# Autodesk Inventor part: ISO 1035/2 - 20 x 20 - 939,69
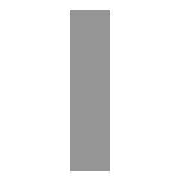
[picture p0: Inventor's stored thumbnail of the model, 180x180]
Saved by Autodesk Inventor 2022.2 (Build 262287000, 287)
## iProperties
IsCustomPart: 1
Created: 2025-02
Part Number: ISO 1035/2 - 20 x 20 - 939,69
Material: Acciaio, Dolce
Description: Barre in acciaio laminate a caldo - Parte 2: barre quadre
Document SubType Name: Modeling
Standard: ISO 1035/2
Designer: 18907419
Standard Revision: First edition 1980-10-15
Standards Organization: ISO
Language: it-IT
Size Designation: 20x 20
Categories: <MemberInstance><Categories><Category DisplayName="Forme strutturali" InternalName="089c4875-fa83-4c05-b084-43b9cc11f5ed" Mnemonic="GRDR"><CategoryParameter Dis
Stock Number: 20x 20
Density: 7.85 g/cm^3
Appearance: Semilucidato
_CCFamilyMember: 168
_CCFamilyDisplayName: ISO 1035/2 - 1980 - Barre in acciaio laminate a caldo - Parte 2: barre quadre
_FrameMemberDoc: Frame Member File
_Version: 15.0.0
_GetPNFromCC: 1
G_L: 939,693 mm
G_W: 20,000 mm
G_H: 20,000 mm
+2362145C-A886-4DE2-AF4E-FECAC0FDEC64+CUTDETAIL1: Angolo retto 45,00 gr
+ABAB8624-30D1-4712-B4D6-8874841F1C4E+CUTDETAIL2: Angolo di taglio 90,00 gr
Author: 18907419
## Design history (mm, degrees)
node "Piano iniziale"
node "Piano finale"
sketch "Schizzo"
  geometry: L1 (10, -10)-(-10, -10); L2 (-10, -10)-(-10, 10); L3 (-10, 10)-(10, 10); L4 (10, 10)-(10, -10); L5 (-6, 0)-(8, 0); L6 (0, -30)-(0, 40); L7 (0, 54)-(0, -44) reference; L8 (-14, 0)-(14, 0) reference
  constraints: 12 end point, 2 collinear, 2 parallel, 1 horizontal, 1 perpendicular
  dimensions: "d0" = 20 distance between parallel lines of L3 L1 (= G_W); "d1" = 20 distance between parallel lines of L4 L2 (= G_H); "d4" = 10 distance between parallel lines of L6 L4 (= 0.5 x d1); "d5" = 10 distance between parallel lines of L5 L3 (= 0.5 x d0)
extrude "Corpo" new body sketch "Schizzo" stored distance "d2" = 939.69262 (= G_L); taper "d3" = 0 deg
node "Driven Length"
  sketch "Sketch3"
    geometry: L1 (0, 0)-(10, 0) reference
    constraints: 2 end point, 1 horizontal
  workplane "Work Plane3"
  sketch "Sketch4" dims "G_H" = 20 [user parameter; used in 1 equation term]
    geometry: L1 (-2, -10)-(12, -10) reference; L2 (-2, 929.693)-(12, 929.693) reference
    dimensions: "d9" = 939.69262 dimension on L1 L2 (derived)
node "Piano di lavoro4"
feature "Divisione1"
node "Piano di lavoro5"
feature "Divisione2"
body "Solid1"
other parameters: "G_W" = 20 [user parameter; used in 1 equation term], "G_L" = 939.69262 (= d9) [user parameter; used in 1 equation term], "d7" = 929.69262 (= G_OFFSET_END + B_L), "B_L" = 939.69262 [user parameter; used in 1 equation term], "d8" = 90 deg
